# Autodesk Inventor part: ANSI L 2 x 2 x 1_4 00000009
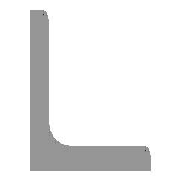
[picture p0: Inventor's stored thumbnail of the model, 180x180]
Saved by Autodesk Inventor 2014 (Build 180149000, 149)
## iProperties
_FrameMemberDoc: Frame Member File
_Version: 15.0.0
_CCFamilyMember: 11
_CCFamilyDisplayName: ANSI L (Equal angles) - Angle Steel
Created: 2007-02
Part Number: ANSI L 2 x 2 x 1_4 00000009
Material: Steel, Mild
Document SubType Name: Modeling
Standard: AISC
Designer: Autodesk, Inc.
Size Designation: L 2 x 2 x 1/4
Stock Number: L 2 x 2 x 1/4
Density: 7.86 g/cm^3
Description: Angle Steel
Standards Organization: ANSI
Language: en-US
Categories: <MemberInstance><Categories><Category DisplayName="Structural Shapes" InternalName="089c4875-fa83-4c05-b084-43b9cc11f5ed" Mnemonic="GRDR"><CategoryParameter Dis
Mass: 4291.52 g
Surface Area: 1807.63 cm^2
Volume: 545.995 cm^3
Appearance: Steel
IsCustomPart: 1
G_L: 37.887 in
G_W: 2.000 in
G_H: 2.000 in
+B8FAFB5A-30E9-45F3-B3BB-CC5B2EBBE4EB+CUTDETAIL1: Notch
+4B281A8D-3DB3-4B15-88BA-5F48458BD7D6+CUTDETAIL2: Cut
+951049C3-EF11-4372-BFEA-D13E83FECF7A+CUTDETAIL3: Notch
+D0F0167F-D03B-496C-B23B-12794DEA7EBF+CUTDETAIL4: Notch
Author: Autodesk, Inc.
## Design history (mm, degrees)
node "Start plane"
node "End plane"
sketch "Sketch"
  geometry: L1 (50.8, 0)-(0, 0); L2 (0, 0)-(0, 50.8); L3 (0, 50.8)-(3.302, 50.8); L4 (6.35, 47.752)-(6.35, 12.7); L5 (12.7, 6.35)-(47.752, 6.35); L6 (50.8, 3.302)-(50.8, 0); L7 (0, -11.041)-(0, 31.538); L8 (-11.041, 0)-(31.538, 0); L9 (0, 63.926)-(0, -23.536) reference; L10 (-23.536, 0)-(63.926, 0) reference; A1 r 6.35 centre (12.7, 12.7) between (6.35, 12.7) and (12.7, 6.35); A2 r 3.048 centre (3.302, 47.752) between (6.35, 47.752) and (3.302, 50.8); A3 r 3.048 centre (47.752, 3.302) between (50.8, 3.302) and (47.752, 6.35); 3 further points
  constraints: 16 end point, 6 point on circle, 6 point on line, 6 tangent, 4 parallel, 3 centre point, 2 collinear, 1 equal radius, 1 horizontal, 1 perpendicular
  dimensions: "d0" = 50.8 distance between parallel lines of L6 L2 (= G_H); "d1" = 50.8 distance between parallel lines of L3 L1 (= G_H); "d2" = 6.35 distance between parallel lines of L2 L4 (= G_T); "d3" = 6.35 distance between parallel lines of L1 L5 (= G_T); "d10" = 0 distance between parallel lines of L7 L2 (computed from ex); "d11" = 0 distance between parallel lines of L8 L1 (computed from d10); "d14" = 6.35 radius of A1 (= G_IR); "d15" = 3.048 radius of A2 (= G_ER)
extrude "Body" new body sketch "Sketch" stored distance "d4" = 962.33018 (= G_L); taper "d5" = 0 deg
node "Driven Length"
  sketch "Sketch6"
    geometry: L1 (0, 0)-(10, 0) reference
    constraints: 2 end point, 1 horizontal
  workplane "Work Plane10"
  sketch "Sketch7"
    geometry: L1 (-2, 7.953)-(12, 7.953) reference; L2 (-2, 970.283)-(12, 970.283) reference
    dimensions: "d23" = 962.33018 distance between parallel lines of L1 L2 (derived)
workplane "Work Plane3"
workplane "Work Plane4"
workplane "Work Plane5"
split "Split1"
workplane "Work Plane6"
workplane "Work Plane7"
workplane "Work Plane8"
workplane "Work Plane9"
workplane "Work Plane11"
workplane "Work Plane12"
workplane "Work Plane13"
body "Solid1"
sketch "Sketch_1"
  geometry: L1 (50.8, 0)-(0, 0); L2 (0, 0)-(0, 50.8); L3 (0, 50.8)-(3.302, 50.8); L4 (6.35, 47.752)-(6.35, 12.7); L5 (12.7, 6.35)-(47.752, 6.35); L6 (50.8, 3.302)-(50.8, 0); A1 r 3.048 centre (3.302, 47.752) between (6.35, 47.752) and (3.302, 50.8); A2 r 6.35 centre (12.7, 12.7) between (6.35, 12.7) and (12.7, 6.35); A3 r 3.048 centre (47.752, 3.302) between (50.8, 3.302) and (47.752, 6.35)
  constraints: 12 end point, 6 point on circle, 3 centre point
extrude "Extrusion2" cut sketch "Sketch_1" stored distance "d24" = 3.302; taper "d25" = 0 deg
sketch "Sketch_2"
  geometry: L1 (50.8, 0)-(0, 0); L2 (0, 0)-(0, 50.8); L3 (0, 50.8)-(3.302, 50.8); L4 (6.35, 47.752)-(6.35, 12.7); L5 (12.7, 6.35)-(47.752, 6.35); L6 (50.8, 3.302)-(50.8, 0); A1 r 3.048 centre (3.302, 47.752) between (6.35, 47.752) and (3.302, 50.8); A2 r 6.35 centre (12.7, 12.7) between (6.35, 12.7) and (12.7, 6.35); A3 r 3.048 centre (47.752, 3.302) between (50.8, 3.302) and (47.752, 6.35)
  constraints: 12 end point, 6 point on circle, 3 centre point
extrude "Extrusion3" cut sketch "Sketch_2" stored distance "d26" = 3.302; taper "d27" = 0 deg
sketch "Sketch_3"
  geometry: L1 (50.8, 0)-(0, 0); L2 (0, 0)-(0, 50.8); L3 (0, 50.8)-(3.302, 50.8); L4 (6.35, 47.752)-(6.35, 12.7); L5 (12.7, 6.35)-(47.752, 6.35); L6 (50.8, 3.302)-(50.8, 0); A1 r 3.048 centre (3.302, 47.752) between (6.35, 47.752) and (3.302, 50.8); A2 r 6.35 centre (12.7, 12.7) between (6.35, 12.7) and (12.7, 6.35); A3 r 3.048 centre (47.752, 3.302) between (50.8, 3.302) and (47.752, 6.35)
  constraints: 12 end point, 6 point on circle, 3 centre point
extrude "Extrusion4" cut sketch "Sketch_3" stored distance "d28" = 3.302; taper "d29" = 0 deg
other parameters: "G_H" = 50.8 [user parameter; used in 2 equation terms], "G_T" = 6.35 [user parameter; used in 2 equation terms], "G_ER" = 3.048 [user parameter; used in 1 equation term], "G_IR" = 6.35 [user parameter; used in 1 equation term], "G_L" = 962.33018 (= d23) [user parameter; used in 1 equation term], "ex" = 0 [user parameter; used in 1 equation term], "G_OFFSET_START" = -7.95314 [user parameter; used in 1 equation term], "G_OFFSET_END" = 0 [user parameter; used in 1 equation term], "d12" = 7.95314 (= -G_OFFSET_START), "d13" = 970.28332 (= G_OFFSET_END + B_L), "B_L" = 970.28332 [user parameter; used in 1 equation term], "d22" = 90 deg
